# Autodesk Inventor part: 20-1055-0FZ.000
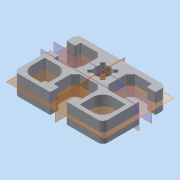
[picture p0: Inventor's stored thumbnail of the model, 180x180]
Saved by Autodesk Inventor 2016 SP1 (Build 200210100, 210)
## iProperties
Created: 2007-12
Document SubType Name: Modeling
Designer: Administrator
Density: 2.75 g/cm^3
Material: EN AW-6063 T66
Description: Profil 45x32 F
Mass: 16.1778 g
Surface Area: 50.1834 cm^2
Volume: 5.88283 cm^3
Part Number: 20-1055-0FZ.000
Vendor: MiniTec
Appearance: Aluminium - flach - Version 1.1
Bezeichnung: Profil 45x32 F
Artikelnr: 201055/0
AIMD_ORIGIN: 00000008
Lieferantennr: 72401
Zeichnungsnr: 20-1055-0FZ.000
MiniTec_ID: 201055/0
Teileart: ART
Lieferant: MiniTec
Länge: 10.0 mm
PV_Stck: 0
M8x20_Stck: 0
Bemerkung: eloxiert E6/EV1
BfGv_Stck: 0
M12_Stck: 0
M10x25_Stck: 0
Title: Profil 45x32 F
Author: Administrator
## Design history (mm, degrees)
sketch "Skizze1"
  geometry: L1 (-4.1, -22.2)-(-4.1, -18.5); L2 (-4.6, -18)-(-6.5, -18); L3 (-6.8, -17.7)-(-6.8, -9.5); L4 (-6.8, -9.5)-(-4.5, -7.2); L5 (-4.5, -7.2)-(4.5, -7.2); L6 (4.5, -7.2)-(6.8, -9.5); L7 (6.8, -9.5)-(6.8, -17.7); L8 (6.5, -18)-(4.6, -18); L9 (4.1, -18.5)-(4.1, -22.2); L10 (-4.4, -22.5)-(-20, -22.5); L11 (-4.384, -2.97)-(-3.419, -2.005); L12 (-3.419, 2.005)-(-4.384, 2.97); L13 (-4.384, 3.394)-(-3.394, 4.384); L14 (-2.97, 4.384)-(-2.005, 3.419); L15 (2.005, 3.419)-(2.97, 4.384); L16 (3.394, 4.384)-(4.384, 3.394); L17 (4.384, 2.97)-(3.419, 2.005); L18 (3.419, -2.005)-(4.384, -2.97); L19 (4.384, -3.394)-(3.394, -4.384); L20 (2.97, -4.384)-(2.005, -3.419); L21 (-2.005, -3.419)-(-2.97, -4.384); L22 (-3.394, -4.384)-(-4.384, -3.394); L23 (13.8, -8.8)-(20, -8.8); L24 (20.5, -9.3)-(20.5, -15.5); L25 (15.5, -20.5)-(9.3, -20.5); L26 (8.8, -20)-(8.8, -13.8); L27 (-20, -8.8)-(-13.8, -8.8); L28 (-8.8, -13.8)-(-8.8, -20); L29 (-9.3, -20.5)-(-15.5, -20.5); L30 (-20.5, -15.5)-(-20.5, -9.3); L31 (20, -22.5)-(4.4, -22.5); L32 (22.5, -4.4)-(22.5, -20); L33 (22.2, -4.1)-(18.5, -4.1); L34 (18, -4.6)-(18, -6.5); L35 (17.7, -6.8)-(9.5, -6.8); L36 (9.5, -6.8)-(7.2, -4.5); L37 (7.2, -4.5)-(7.2, 4.5); L38 (7.2, 4.5)-(9.5, 6.8); L39 (9.5, 6.8)-(17.7, 6.8); L40 (18, 6.5)-(18, 4.6); L41 (18.5, 4.1)-(22.2, 4.1); L42 (22.5, 7)-(22.5, 4.4); L43 (-20, 9.5)-(20, 9.5); L44 (-22.5, 4.4)-(-22.5, 7); L45 (-22.2, 4.1)-(-18.5, 4.1); L46 (-18, 4.6)-(-18, 6.5); L47 (-17.7, 6.8)-(-9.5, 6.8); L48 (-9.5, 6.8)-(-7.2, 4.5); L49 (-7.2, 4.5)-(-7.2, -4.5); L50 (-7.2, -4.5)-(-9.5, -6.8); L51 (-9.5, -6.8)-(-17.7, -6.8); L52 (-18, -6.5)-(-18, -4.6); L53 (-18.5, -4.1)-(-22.2, -4.1); L54 (-22.5, -20)-(-22.5, -4.4); A1 r 0.3 centre (-4.4, -22.2) between (-4.4, -22.5) and (-4.1, -22.2); A2 r 0.5 centre (-4.6, -18.5) between (-4.1, -18.5) and (-4.6, -18); A3 r 0.3 centre (-6.5, -17.7) between (-6.8, -17.7) and (-6.5, -18); A4 r 0.3 centre (6.5, -17.7) between (6.5, -18) and (6.8, -17.7); A5 r 0.5 centre (4.6, -18.5) between (4.6, -18) and (4.1, -18.5); A6 r 0.3 centre (4.4, -22.2) between (4.1, -22.2) and (4.4, -22.5); A7 r 0.3 centre (-4.172, -3.182) between (-4.384, -2.97) and (-4.384, -3.394); A8 r 0.3 centre (-3.631, -1.793) between (-3.419, -2.005) and (-3.362, -1.66); A9 r 3.75 centre (0, 0) between (-3.362, 1.66) and (-3.362, -1.66); A10 r 0.3 centre (-3.631, 1.793) between (-3.362, 1.66) and (-3.419, 2.005); A11 r 0.3 centre (-4.172, 3.182) between (-4.384, 3.394) and (-4.384, 2.97); A12 r 0.3 centre (-3.182, 4.172) between (-2.97, 4.384) and (-3.394, 4.384); A13 r 0.3 centre (-1.793, 3.631) between (-2.005, 3.419) and (-1.66, 3.362); A14 r 3.75 centre (0, 0) between (1.66, 3.362) and (-1.66, 3.362); A15 r 0.3 centre (1.793, 3.631) between (1.66, 3.362) and (2.005, 3.419); A16 r 0.3 centre (3.182, 4.172) between (3.394, 4.384) and (2.97, 4.384); A17 r 0.3 centre (4.172, 3.182) between (4.384, 2.97) and (4.384, 3.394); A18 r 0.3 centre (3.631, 1.793) between (3.419, 2.005) and (3.362, 1.66); A19 r 3.75 centre (0, 0) between (3.362, -1.66) and (3.362, 1.66); A20 r 0.3 centre (3.631, -1.793) between (3.362, -1.66) and (3.419, -2.005); A21 r 0.3 centre (4.172, -3.182) between (4.384, -3.394) and (4.384, -2.97); A22 r 0.3 centre (3.182, -4.172) between (2.97, -4.384) and (3.394, -4.384); A23 r 0.3 centre (1.793, -3.631) between (2.005, -3.419) and (1.66, -3.362); A24 r 3.75 centre (0, 0) between (-1.66, -3.362) and (1.66, -3.362); A25 r 0.3 centre (-1.793, -3.631) between (-1.66, -3.362) and (-2.005, -3.419); A26 r 0.3 centre (-3.182, -4.172) between (-3.394, -4.384) and (-2.97, -4.384); A27 r 5 centre (13.8, -13.8) between (13.8, -8.8) and (8.8, -13.8); A28 r 0.5 centre (20, -9.3) between (20.5, -9.3) and (20, -8.8); A29 r 5 centre (15.5, -15.5) between (15.5, -20.5) and (20.5, -15.5); A30 r 0.5 centre (9.3, -20) between (8.8, -20) and (9.3, -20.5); A31 r 0.5 centre (-20, -9.3) between (-20, -8.8) and (-20.5, -9.3); A32 r 5 centre (-13.8, -13.8) between (-8.8, -13.8) and (-13.8, -8.8); A33 r 0.5 centre (-9.3, -20) between (-9.3, -20.5) and (-8.8, -20); A34 r 5 centre (-15.5, -15.5) between (-20.5, -15.5) and (-15.5, -20.5); A35 r 2.5 centre (20, -20) between (20, -22.5) and (22.5, -20); A36 r 0.3 centre (22.2, -4.4) between (22.5, -4.4) and (22.2, -4.1); A37 r 0.5 centre (18.5, -4.6) between (18.5, -4.1) and (18, -4.6); A38 r 0.3 centre (17.7, -6.5) between (17.7, -6.8) and (18, -6.5); A39 r 0.3 centre (17.7, 6.5) between (18, 6.5) and (17.7, 6.8); A40 r 0.5 centre (18.5, 4.6) between (18, 4.6) and (18.5, 4.1); A41 r 0.3 centre (22.2, 4.4) between (22.2, 4.1) and (22.5, 4.4); A42 r 2.5 centre (20, 7) between (22.5, 7) and (20, 9.5); A43 r 2.5 centre (-20, 7) between (-20, 9.5) and (-22.5, 7); A44 r 0.3 centre (-22.2, 4.4) between (-22.5, 4.4) and (-22.2, 4.1); A45 r 0.5 centre (-18.5, 4.6) between (-18.5, 4.1) and (-18, 4.6); A46 r 0.3 centre (-17.7, 6.5) between (-17.7, 6.8) and (-18, 6.5); A47 r 0.3 centre (-17.7, -6.5) between (-18, -6.5) and (-17.7, -6.8); A48 r 0.5 centre (-18.5, -4.6) between (-18, -4.6) and (-18.5, -4.1); A49 r 0.3 centre (-22.2, -4.4) between (-22.2, -4.1) and (-22.5, -4.4); A50 r 2.5 centre (-20, -20) between (-22.5, -20) and (-20, -22.5)
  constraints: 108 end point, 100 point on circle, 50 centre point
extrude "Extrusion1" new body sketch "Skizze1" taper "d1" = 0 deg; stored distance "do" = 10 (= Länge)
workaxis "Arbeitsachse1"
  workplane "Arbeitsebene1"
node "Volumenkörper1"
node "Volumenkörpern"
node "Oberflächenkörpern"
other parameters: "M8x20_Stck" = 0 [user parameter], "PV_Stck" = 0 [user parameter], "Länge" = 10 [user parameter; used in 1 equation term], "M10x25_Stck" = 0 [user parameter], "M12_Stck" = 0 [user parameter], "BfGv_Stck" = 0 [user parameter], "d14" = 0, "d15" = 0, "d16" = 0, "d17" = 0, "d18" = 0, "d19" = 0
